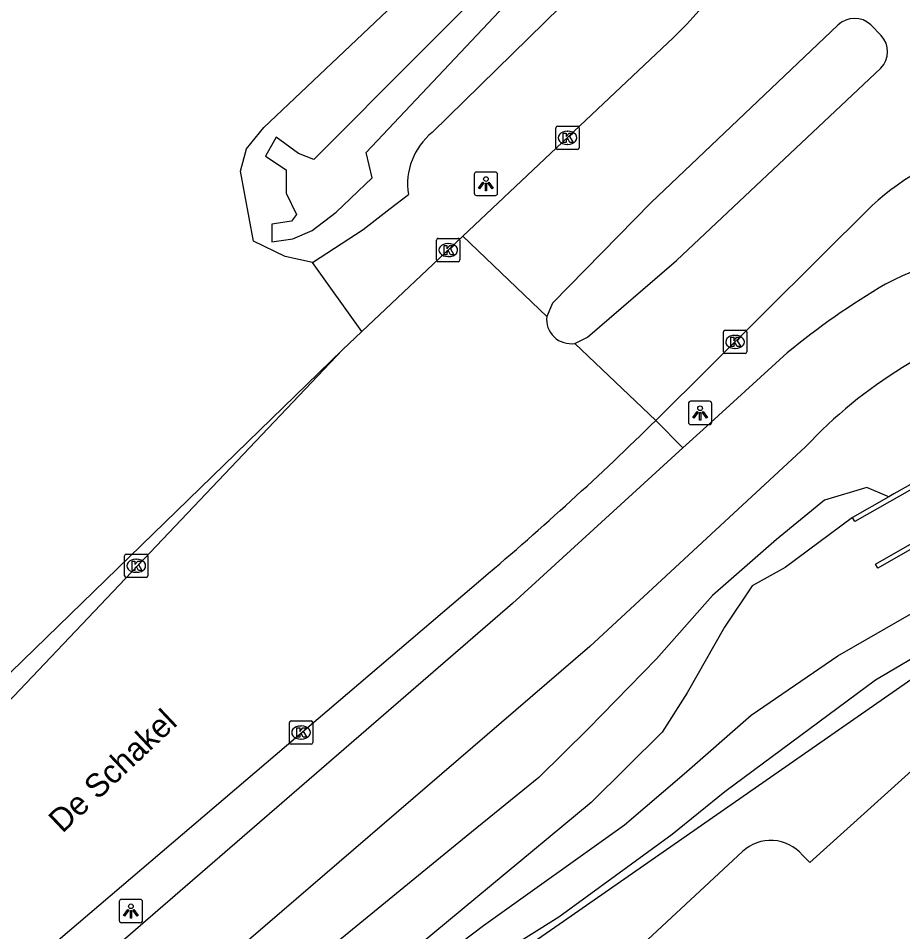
# Model space of a CAD drawing. Extents: x 156141 to 158132, y 385651 to 388399.
# Drawn here: x 156557 to 156594.82, y 387599.4 to 387638.46 of the extents above; entities that cross this region are included whole.
import ezdxf

# ---------------------------------------------------------------- set-up
doc = ezdxf.new("R2010")
doc.units = 0
for name, color, linetype in [('IMGEO_Berm_groen', 7, 'Continuous'), ('IMGEO_Erf', 7, 'Continuous'), ('IMGEO_Fietspad_gesloten', 7, 'Continuous'), ('IMGEO_Groenvoorziening', 7, 'Continuous'), ('IMGEO_Hek', 7, 'Continuous'), ('IMGEO_Kolk', 7, 'Continuous'), ('IMGEO_Lichtpunt', 7, 'Continuous'), ('IMGEO_Muur', 7, 'Continuous'), ('IMGEO_Openbare_ruimte_label', 7, 'Continuous'), ('IMGEO_Rijbaan_lokaal_gesloten', 7, 'Continuous'), ('IMGEO_Waterloop', 7, 'Continuous')]:
    doc.layers.add(name, color=color, linetype=linetype)

msp = doc.modelspace()

# ---------------------------------------------------------------- linework, layer by layer
at = {"layer": 'IMGEO_Berm_groen'}
for points in [[(156574.703, 387633.583), (156582.934, 387641.666)], [(156569.586, 387628.024), (156571.751, 387629.426), (156572.901, 387630.323), (156573.681, 387630.93)], [(156571.693, 387625.069), (156569.586, 387628.024)], [(156584.258, 387621.261), (156585.415, 387620.086)], [(156594.228, 387618.002), (156594.161, 387618.028), (156593.291, 387618.392), (156591.481, 387617.853), (156589.419, 387616.17), (156586.681, 387613.782), (156584.292, 387611.071), (156581.372, 387608.069), (156579.258, 387605.991), (156576.15, 387603.478), (156569.414, 387597.957), (156564.654, 387593.969), (156560.852, 387590.786), (156558.247, 387588.454), (156557.775, 387587.764), (156557.476, 387586.854), (156557.603, 387586.343), (156559.305, 387584.578), (156559.905, 387584.391), (156560.52, 387584.454), (156562.689, 387585.819)]]:
    msp.add_lwpolyline(points, dxfattribs=at)
msp.add_arc((156576.5, 387631.367), 2.853, 129.0442, 188.82, dxfattribs=at)
at = {"layer": 'IMGEO_Erf'}
msp.add_lwpolyline([(156569.586, 387628.024), (156568.413, 387628.275), (156567.055, 387628.928), (156566.497, 387631.918), (156566.751, 387632.873), (156567.5, 387633.796), (156575.957, 387641.808)], dxfattribs=at)
at = {"layer": 'IMGEO_Fietspad_gesloten'}
for points in [[(156585.415, 387620.086), (156586.283, 387620.878), (156589.88, 387624.16)], [(156585.415, 387620.086), (156578.126, 387613.433), (156551.398, 387590.304), (156495.527, 387537.568), (156379.452, 387427.902)], [(156590.669, 387620.135), (156581.442, 387611.597), (156554.376, 387588.321), (156498.217, 387535.194), (156430.268, 387471.316), (156381.614, 387425.402)]]:
    msp.add_lwpolyline(points, dxfattribs=at)
for centre, radius, start, end in [((156603.767, 387607.976), 21.427, 82.6392, 116.8474), ((156611.128, 387598.158), 33.58, 120.491, 129.2552), ((156605.279, 387606.513), 19.975, 106.2296, 137.0031)]:
    msp.add_arc(centre, radius, start, end, dxfattribs=at)
at = {"layer": 'IMGEO_Groenvoorziening'}
msp.add_lwpolyline([(156562.689, 387585.819), (156570.318, 387592.668), (156574.157, 387595.767), (156577.521, 387598.409), (156580.111, 387600.038), (156584.957, 387603.57), (156587.219, 387605.389), (156593.652, 387610.168), (156595.879, 387611.476), (156598.448, 387613.109), (156599.494, 387613.824)], dxfattribs=at)
at = {"layer": 'IMGEO_Hek'}
for points in [[(156570.86, 387624.283), (156551.599, 387605.578)], [(156646.881, 387477.996), (156638.619, 387470.479), (156638.602, 387470.464), (156602.22, 387437.666), (156601.882, 387437.361), (156590.708, 387427.281), (156590.403, 387427.007), (156590.376, 387426.982), (156553.024, 387393.236), (156505.235, 387445.99), (156463.944, 387491.685), (156532.587, 387555.868), (156577.395, 387597.823), (156580.308, 387599.849), (156603.227, 387615.785)]]:
    msp.add_lwpolyline(points, dxfattribs=at)
at = {"layer": 'IMGEO_Kolk'}
for p, q in [((156579.985, 387632.926), (156579.985, 387633.778)), ((156580.06, 387633.852), (156580.912, 387633.852)), ((156580.986, 387633.778), (156580.986, 387632.926)), ((156580.473, 387633.632), (156580.498, 387633.632)), ((156580.496, 387633.072), (156580.471, 387633.072)), ((156580.912, 387632.852), (156580.06, 387632.852)), ((156574.96, 387629.052), (156575.812, 387629.052)), ((156574.885, 387628.126), (156574.885, 387628.978)), ((156575.373, 387628.832), (156575.398, 387628.832)), ((156575.886, 387628.978), (156575.886, 387628.126)), ((156575.396, 387628.272), (156575.371, 387628.272)), ((156575.812, 387628.052), (156574.96, 387628.052)), ((156587.225, 387625.121), (156588.077, 387625.121)), ((156587.15, 387624.195), (156587.15, 387625.047)), ((156587.638, 387624.901), (156587.663, 387624.901)), ((156588.151, 387625.047), (156588.151, 387624.195)), ((156587.661, 387624.341), (156587.636, 387624.341)), ((156588.077, 387624.121), (156587.225, 387624.121)), ((156561.543, 387614.623), (156561.543, 387615.475)), ((156561.618, 387615.549), (156562.47, 387615.549)), ((156562.544, 387615.475), (156562.544, 387614.623)), ((156562.031, 387615.329), (156562.056, 387615.329)), ((156562.054, 387614.769), (156562.029, 387614.769)), ((156562.47, 387614.549), (156561.618, 387614.549)), ((156568.59, 387607.491), (156568.59, 387608.343)), ((156568.665, 387608.417), (156569.517, 387608.417)), ((156569.591, 387608.343), (156569.591, 387607.491)), ((156569.078, 387608.197), (156569.103, 387608.197)), ((156569.101, 387607.637), (156569.076, 387607.637)), ((156569.517, 387607.417), (156568.665, 387607.417))]:
    msp.add_line(p, q, dxfattribs=at)
for points in [[(156579.985, 387632.926), (156579.985, 387633.778)], [(156580.06, 387633.852), (156580.912, 387633.852)], [(156580.986, 387633.778), (156580.986, 387632.926)], [(156580.306, 387633.552), (156580.429, 387633.552), (156580.429, 387633.401), (156580.559, 387633.552), (156580.723, 387633.552), (156580.577, 387633.401), (156580.73, 387633.152), (156580.578, 387633.152), (156580.493, 387633.316), (156580.429, 387633.249), (156580.429, 387633.152), (156580.306, 387633.152), (156580.306, 387633.552)], [(156580.912, 387632.852), (156580.06, 387632.852)], [(156574.96, 387629.052), (156575.812, 387629.052)], [(156574.885, 387628.126), (156574.885, 387628.978)], [(156575.206, 387628.752), (156575.329, 387628.752), (156575.329, 387628.601), (156575.459, 387628.752), (156575.623, 387628.752), (156575.477, 387628.601), (156575.63, 387628.352), (156575.478, 387628.352), (156575.393, 387628.516), (156575.329, 387628.449), (156575.329, 387628.352), (156575.206, 387628.352), (156575.206, 387628.752)], [(156575.886, 387628.978), (156575.886, 387628.126)], [(156575.812, 387628.052), (156574.96, 387628.052)], [(156587.225, 387625.121), (156588.077, 387625.121)], [(156587.15, 387624.195), (156587.15, 387625.047)], [(156587.471, 387624.821), (156587.594, 387624.821), (156587.594, 387624.67), (156587.724, 387624.821), (156587.888, 387624.821), (156587.742, 387624.67), (156587.895, 387624.421), (156587.743, 387624.421), (156587.658, 387624.585), (156587.594, 387624.518), (156587.594, 387624.421), (156587.471, 387624.421), (156587.471, 387624.821)], [(156588.151, 387625.047), (156588.151, 387624.195)], [(156588.077, 387624.121), (156587.225, 387624.121)], [(156561.543, 387614.623), (156561.543, 387615.475)], [(156561.618, 387615.549), (156562.47, 387615.549)], [(156562.544, 387615.475), (156562.544, 387614.623)], [(156561.864, 387615.249), (156561.987, 387615.249), (156561.987, 387615.098), (156562.117, 387615.249), (156562.281, 387615.249), (156562.135, 387615.098), (156562.288, 387614.849), (156562.136, 387614.849), (156562.051, 387615.013), (156561.987, 387614.946), (156561.987, 387614.849), (156561.864, 387614.849), (156561.864, 387615.249)], [(156562.47, 387614.549), (156561.618, 387614.549)], [(156568.59, 387607.491), (156568.59, 387608.343)], [(156568.665, 387608.417), (156569.517, 387608.417)], [(156569.591, 387608.343), (156569.591, 387607.491)], [(156568.911, 387608.117), (156569.034, 387608.117), (156569.034, 387607.966), (156569.164, 387608.117), (156569.328, 387608.117), (156569.182, 387607.966), (156569.335, 387607.717), (156569.183, 387607.717), (156569.098, 387607.881), (156569.034, 387607.814), (156569.034, 387607.717), (156568.911, 387607.717), (156568.911, 387608.117)], [(156569.517, 387607.417), (156568.665, 387607.417)]]:
    msp.add_lwpolyline(points, dxfattribs=at)
for centre, start, end in [((156580.062, 387633.776), 91.552, 178.448), ((156580.062, 387633.776), 91.552, 178.448), ((156580.91, 387633.776), 1.552, 88.448), ((156580.91, 387633.776), 1.552, 88.448), ((156580.062, 387632.928), 181.552, 268.448), ((156580.062, 387632.928), 181.552, 268.448), ((156580.91, 387632.928), 271.552, 358.448), ((156580.91, 387632.928), 271.552, 358.448), ((156574.962, 387628.976), 91.552, 178.448), ((156574.962, 387628.976), 91.552, 178.448), ((156575.81, 387628.976), 1.552, 88.448), ((156575.81, 387628.976), 1.552, 88.448), ((156574.962, 387628.128), 181.552, 268.448), ((156574.962, 387628.128), 181.552, 268.448), ((156575.81, 387628.128), 271.552, 358.448), ((156575.81, 387628.128), 271.552, 358.448), ((156587.227, 387625.045), 91.552, 178.448), ((156587.227, 387625.045), 91.552, 178.448), ((156588.075, 387625.045), 1.552, 88.448), ((156588.075, 387625.045), 1.552, 88.448), ((156587.227, 387624.197), 181.552, 268.448), ((156587.227, 387624.197), 181.552, 268.448), ((156588.075, 387624.197), 271.552, 358.448), ((156588.075, 387624.197), 271.552, 358.448), ((156561.62, 387615.473), 91.552, 178.448), ((156561.62, 387615.473), 91.552, 178.448), ((156562.468, 387615.473), 1.552, 88.448), ((156562.468, 387615.473), 1.552, 88.448), ((156561.62, 387614.625), 181.552, 268.448), ((156561.62, 387614.625), 181.552, 268.448), ((156562.468, 387614.625), 271.552, 358.448), ((156562.468, 387614.625), 271.552, 358.448), ((156568.667, 387608.341), 91.552, 178.448), ((156568.667, 387608.341), 91.552, 178.448), ((156569.515, 387608.341), 1.552, 88.448), ((156569.515, 387608.341), 1.552, 88.448), ((156568.667, 387607.493), 181.552, 268.448), ((156568.667, 387607.493), 181.552, 268.448), ((156569.515, 387607.493), 271.552, 358.448), ((156569.515, 387607.493), 271.552, 358.448)]:
    msp.add_arc(centre, 0.0765, start, end, dxfattribs=at)
for centre, major_axis, ratio, start_param, end_param in [((156580.472, 387633.352), (-0.387, 0.002), 0.722429, 4.712389, 7.853982), ((156580.497, 387633.352), (-0.39, 0.002), 0.717154, 1.570796, 4.712389), ((156575.372, 387628.552), (-0.387, 0.002), 0.722429, 4.712389, 7.853982), ((156575.397, 387628.552), (-0.39, 0.002), 0.717154, 1.570796, 4.712389), ((156587.637, 387624.621), (-0.387, 0.002), 0.722429, 4.712389, 7.853982), ((156587.662, 387624.621), (-0.39, 0.002), 0.717154, 1.570796, 4.712389), ((156562.03, 387615.049), (-0.387, 0.002), 0.722429, 4.712389, 7.853982), ((156562.055, 387615.049), (-0.39, 0.002), 0.717154, 1.570796, 4.712389), ((156569.077, 387607.917), (-0.387, 0.002), 0.722429, 4.712389, 7.853982), ((156569.102, 387607.917), (-0.39, 0.002), 0.717154, 1.570796, 4.712389)]:
    msp.add_ellipse(centre, major_axis=major_axis, ratio=ratio, start_param=start_param, end_param=end_param, dxfattribs=at)
at = {"layer": 'IMGEO_Lichtpunt'}
for p, q in [((156576.497, 387631.791), (156576.497, 387630.984)), ((156576.497, 387631.791), (156576.497, 387630.984)), ((156577.399, 387631.886), (156576.591, 387631.886)), ((156577.399, 387631.886), (156576.591, 387631.886)), ((156577.493, 387630.984), (156577.493, 387631.791)), ((156577.493, 387630.984), (156577.493, 387631.791)), ((156576.591, 387630.89), (156577.399, 387630.89)), ((156576.591, 387630.89), (156577.399, 387630.89)), ((156585.657, 387621.987), (156585.657, 387621.18)), ((156585.657, 387621.987), (156585.657, 387621.18)), ((156586.559, 387622.082), (156585.751, 387622.082)), ((156586.559, 387622.082), (156585.751, 387622.082)), ((156586.653, 387621.18), (156586.653, 387621.987)), ((156586.653, 387621.18), (156586.653, 387621.987)), ((156585.751, 387621.086), (156586.559, 387621.086)), ((156585.751, 387621.086), (156586.559, 387621.086)), ((156561.314, 387600.687), (156561.314, 387599.88)), ((156561.314, 387600.687), (156561.314, 387599.88)), ((156562.216, 387600.782), (156561.408, 387600.782)), ((156562.216, 387600.782), (156561.408, 387600.782)), ((156562.31, 387599.88), (156562.31, 387600.687)), ((156562.31, 387599.88), (156562.31, 387600.687)), ((156561.408, 387599.786), (156562.216, 387599.786)), ((156561.408, 387599.786), (156562.216, 387599.786))]:
    msp.add_line(p, q, dxfattribs=at)
for points in [[(156576.871, 387631.455), (156576.91, 387631.427), (156576.722, 387631.165), (156576.684, 387631.192), (156576.871, 387631.455)], [(156576.973, 387631.407), (156577.02, 387631.407), (156577.02, 387631.085), (156576.973, 387631.085), (156576.973, 387631.407)], [(156577.083, 387631.427), (156577.121, 387631.454), (156577.308, 387631.192), (156577.269, 387631.164), (156577.083, 387631.427)], [(156586.031, 387621.651), (156586.07, 387621.623), (156585.882, 387621.361), (156585.844, 387621.388), (156586.031, 387621.651)], [(156586.133, 387621.603), (156586.18, 387621.603), (156586.18, 387621.281), (156586.133, 387621.281), (156586.133, 387621.603)], [(156586.243, 387621.623), (156586.281, 387621.65), (156586.468, 387621.388), (156586.429, 387621.36), (156586.243, 387621.623)], [(156561.688, 387600.351), (156561.727, 387600.323), (156561.539, 387600.061), (156561.501, 387600.088), (156561.688, 387600.351)], [(156561.79, 387600.303), (156561.837, 387600.303), (156561.837, 387599.981), (156561.79, 387599.981), (156561.79, 387600.303)], [(156561.9, 387600.323), (156561.938, 387600.35), (156562.125, 387600.088), (156562.086, 387600.06), (156561.9, 387600.323)]]:
    msp.add_lwpolyline(points, dxfattribs=at)
for centre in [(156576.996, 387631.589), (156586.156, 387621.785), (156561.813, 387600.485)]:
    msp.add_circle(centre, 0.0994, dxfattribs=at)
for centre, start, end in [((156576.591, 387631.791), 90, 180), ((156576.591, 387631.791), 90, 180), ((156577.399, 387631.791), 0, 90), ((156577.399, 387631.791), 0, 90), ((156576.591, 387630.984), 180, 270), ((156576.591, 387630.984), 180, 270), ((156577.399, 387630.984), 270, 0), ((156577.399, 387630.984), 270, 360), ((156585.751, 387621.987), 90, 180), ((156585.751, 387621.987), 90, 180), ((156586.559, 387621.987), 0, 90), ((156586.559, 387621.987), 0, 90), ((156585.751, 387621.18), 180, 270), ((156585.751, 387621.18), 180, 270), ((156586.559, 387621.18), 270, 0), ((156586.559, 387621.18), 270, 360), ((156561.408, 387600.687), 90, 180), ((156561.408, 387600.687), 90, 180), ((156562.216, 387600.687), 0, 90), ((156562.216, 387600.687), 0, 90), ((156561.408, 387599.88), 180, 270), ((156561.408, 387599.88), 180, 270), ((156562.216, 387599.88), 270, 0), ((156562.216, 387599.88), 270, 360)]:
    msp.add_arc(centre, 0.0946, start, end, dxfattribs=at)
at = {"layer": 'IMGEO_Muur'}
for points in [[(156568.978, 387632.686), (156568.027, 387633.385), (156567.574, 387632.56), (156568.459, 387631.989)], [(156568.683, 387629.782), (156567.841, 387629.656), (156567.845, 387628.898), (156568.744, 387629.038)], [(156595.886, 387617.562), (156595.284, 387618.603), (156594.439, 387618.122), (156594.228, 387618.002)], [(156596.492, 387616.512), (156593.76, 387614.944), (156593.66, 387615.117), (156596.218, 387616.586), (156595.21, 387618.331), (156592.775, 387616.945), (156592.676, 387617.118)], [(156594.228, 387618.002), (156592.676, 387617.118)]]:
    msp.add_lwpolyline(points, dxfattribs=at)
at = {"layer": 'IMGEO_Rijbaan_lokaal_gesloten'}
for points in [[(156592.052, 387638.164), (156584.069, 387630.584), (156579.847, 387626.274), (156579.595, 387625.712)], [(156593.892, 387637.722), (156593.463, 387638.178)], [(156576.006, 387629.138), (156585.024, 387637.643)], [(156580.802, 387624.56), (156581.34, 387624.826), (156585.141, 387628.102), (156593.886, 387636.335)], [(156593.507, 387630.452), (156584.258, 387621.261)], [(156571.693, 387625.069), (156576.006, 387629.138)], [(156579.595, 387625.712), (156576.006, 387629.138)], [(156553.077, 387605.55), (156570.86, 387624.283), (156571.693, 387625.069)], [(156584.258, 387621.261), (156580.802, 387624.56)], [(156379.528, 387430.462), (156494.497, 387538.848), (156552.666, 387593.555), (156552.503, 387593.766), (156576.876, 387614.53)], [(156590.53, 387602.679), (156590.849, 387602.362), (156595.631, 387606.677)], [(156466.435, 387489.763), (156478.39, 387500.9), (156479.281, 387501.735), (156480.114, 387502.834), (156480.58, 387503.254), (156481.503, 387503.777), (156497.027, 387518.253), (156529.401, 387548.361), (156559.408, 387576.269), (156587.969, 387602.829)]]:
    msp.add_lwpolyline(points, dxfattribs=at)
for centre, radius, start, end in [((156574.707, 387648.418), 14.918, 313.7562, 2.0852), ((156592.765, 387637.454), 1.006, 46.0172, 135.1198), ((156593.195, 387637.032), 0.981, 314.7883, 44.716), ((156601.451, 387621.766), 11.771, 78.7294, 132.4451), ((156580.63, 387625.588), 1.042, 173.1477, 279.5235), ((156491.632, 387715.432), 132.089, 310.19177, 314.52613), ((156589.178, 387601.532), 1.773, 40.3084, 132.9875)]:
    msp.add_arc(centre, radius, start, end, dxfattribs=at)
at = {"layer": 'IMGEO_Waterloop'}
for points in [[(156581.287, 387644.119), (156574.161, 387636.953), (156569.644, 387632.423), (156568.978, 387632.686), (156568.027, 387633.385), (156567.574, 387632.56), (156568.459, 387631.989), (156568.453, 387630.977), (156568.898, 387630.067), (156568.683, 387629.782), (156567.841, 387629.656), (156567.845, 387628.898), (156568.744, 387629.038), (156569.564, 387629.383), (156570.588, 387630.177), (156572.129, 387631.634), (156571.882, 387632.723), (156581.595, 387643.051)], [(156592.676, 387617.118), (156589.793, 387614.971), (156588.376, 387614.191), (156587.206, 387612.425), (156585.604, 387609.612), (156584.536, 387607.928), (156581.497, 387604.93), (156564.947, 387591.193)], [(156574.012, 387597.487), (156576.887, 387599.663), (156582.924, 387603.975), (156585.47, 387606.152), (156588.345, 387608.657), (156592.041, 387611.203), (156595.203, 387613.01), (156597.113, 387614.304), (156598.181, 387614.673), (156599.043, 387614.92), (156599.29, 387615.166), (156599.033, 387616.265), (156597.472, 387616.676), (156596.492, 387616.512)]]:
    msp.add_lwpolyline(points, dxfattribs=at)

# ---------------------------------------------------------------- texts
at = {"layer": 'IMGEO_Openbare_ruimte_label'}
msp.add_text('De Schakel', height=1, rotation=43.338, dxfattribs=at).set_placement((156558.882, 387603.581))

doc.saveas('drawing.dxf')
